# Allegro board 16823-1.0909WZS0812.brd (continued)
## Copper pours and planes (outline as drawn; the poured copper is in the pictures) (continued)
PWR_CHG_HIDRV on TOP: 163.25,162.79 163.11,162.93 163.11,165.06 163.23,165.18 163.91,165.18 164.09,165 164.09,162.84 164.04,162.79
PWR_CHG_LODRV on TOP: 170.09,158.63 170.01,158.7 170.01,160.5 170.03,160.53 171.3,160.53 171.41,160.43 171.41,158.75 171.28,158.63
PWR_CHG_PHASE on TOP: 167.32,161.01 167.14,161.19 167.14,162.69 167.01,162.82 164.32,162.82 164.29,162.84 164.29,164.67 164.37,164.75 166.53,164.75 166.68,164.9 166.68,169.88 166.96,170.16 171.43,170.16 171.66,169.93 171.66,161.57 171.1,161.01
PWR_CHG_PHASE on BOTTOM: 170.06,163.17 169.98,163.25 169.98,164.09 169.83,164.24 166.86,164.24 166.68,164.42 166.68,169.88 166.96,170.16 171.43,170.16 171.66,169.93 171.66,163.27 171.56,163.17
PWR_DCBATOUT_3D3V on TOP: 41.56,54.66 41.36,54.87 41.36,58.68 41.54,58.85 49.38,58.85 49.61,58.63 49.61,54.71 49.56,54.66 ; 2 cut-outs
PWR_DCBATOUT_5V on TOP: 41.43,38.58 41.36,38.66 41.36,42.39 41.43,42.47 49.49,42.47 49.61,42.34 49.61,38.76 49.44,38.58 ; 2 cut-outs
PWR_DCBATOUT_VCCGI on TOP: 111.95,125.73 111.64,126.04 111.64,134.95 111.72,135.03 115.4,135.03 115.53,134.9 115.53,131.29 115.3,131.07 115.3,125.76 115.27,125.73
PWR_DCBATOUT_VCCGI on BOTTOM: 114.43,125.73 114.41,125.76 114.41,127.13 114.23,127.31 111.87,127.31 111.64,127.54 111.64,135.74 111.72,135.82 115.37,135.82 115.53,135.66 115.53,131.29 115.3,131.07 115.3,125.76 115.27,125.73
PWR_DCBATOUT_VDDQ on TOP: 60,30.41 59.88,30.53 59.88,32.77 58.02,34.62 57.31,34.62 57.21,34.72 57.21,35.87 57.23,35.89 62.57,35.89 62.77,35.69 62.77,34.5 62.78,34.48 62.78,34.2 63.1,33.89 65.74,33.89 65.95,33.68 65.95,30.79 65.56,30.41
PWR_DCBATOUT_VNN on TOP: 107.12,127.84 106.97,127.99 106.97,133.68 107.09,133.81 111.28,133.81 111.44,133.66 111.44,128.2 111.08,127.84
PWR_VCCGI_PH on TOP: 114.08,121.85 113.8,122.13 113.8,125.33 113.98,125.5 115.53,125.5 115.68,125.66 115.68,130.94 115.81,131.07 118.6,131.07 118.68,130.99 118.68,126.14 119.01,125.81 119.44,125.81 119.51,125.73 119.51,125.3 119.82,125 120.15,125 120.33,124.82 120.33,121.92 120.25,121.85 ; 1 cut-out
PWR_VCCGI_PH on BOTTOM: 114.08,121.85 113.8,122.13 113.8,125.33 113.98,125.5 115.53,125.5 115.68,125.66 115.68,130.94 115.81,131.07 118.6,131.07 118.68,130.99 118.68,126.14 119.01,125.81 119.44,125.81 120.33,124.92 120.33,121.92 120.25,121.85
PWR_VCCRAM_PH on BOTTOM: 138.67,126.24 138.39,126.52 138.39,128.2 137.98,128.6 136.05,128.6 136,128.65 136,129.16 136.05,129.21 139.83,129.21 139.91,129.14 139.91,126.32 139.83,126.24
PWR_VDDQ on TOP: 73.41,40.85 73.24,41.02 73.24,43.97 73.25,43.98 73.25,46.46 74.33,47.54 74.33,52.58 77.86,56.11 82.74,56.11 83.04,55.81 83.04,54.15 83.34,53.85 90.76,53.85 90.96,53.65 90.96,43.74 90.36,43.13 83.5,43.13 81.21,40.85 ; 12 cut-outs
PWR_VDDQ on BOTTOM: 69.43,40.77 69.3,40.9 69.3,43.08 69.88,43.66 69.88,45.16 70.16,45.44 74.84,45.44 75.14,45.14 75.14,40.97 74.94,40.77 ; 5 cut-outs
PWR_VDDQ_PH on TOP: 66.4,30.33 66.33,30.41 66.33,32.06 66.4,32.13 67.55,32.13 67.8,32.39 67.8,33.94 67.42,34.32 64.62,34.32 64.55,34.39 64.55,37.77 64.6,37.82 73.03,37.82 73.29,37.57 73.29,30.96 72.65,30.33
PWR_VDDQ_PH on BOTTOM: 68.21,30.86 67.47,31.6 67.47,37.67 67.57,37.77 73.08,37.77 73.29,37.57 73.29,31.83 72.32,30.86
PWR_VNN_PH on TOP: 100.64,124.51 100.49,124.67 100.49,129.08 100.59,129.19 103.84,129.19 103.99,129.03 103.99,127.64 104.25,127.38 109.25,127.38 109.3,127.33 109.3,124.87 108.95,124.51 ; 2 cut-outs
PWR_VNN_PH on BOTTOM: 100.67,124.51 100.52,124.67 100.52,127.13 100.77,127.38 109.25,127.38 109.3,127.33 109.3,124.84 108.97,124.51
RING2 on TOP: 169.86,15.67 169.63,15.9 168.43,15.9 166.33,18.01 166.33,19.41 165.36,20.37 165.36,21.31 165.56,21.52 166.4,21.52 166.5,21.41 166.5,20.73 167.93,19.31 167.93,18.24 168.66,17.5 169.48,17.5 169.76,17.22 171.1,17.22 171.28,17.05 171.28,15.9 171.05,15.67 ; 1 cut-out
RING2_R on TOP: 171.56,16.08 171.41,16.23 171.41,17.07 171.51,17.17 173.9,17.17 173.97,17.1 173.97,16.13 173.92,16.08
RING2_R on BOTTOM: 171.25,15.9 171.13,16.03 171.13,16.99 171.33,17.2 173.49,17.2 173.64,17.05 173.64,16.08 173.46,15.9
RTC_AUX_S5 on BOTTOM: 102.67,97.13 102.39,97.16 101.89,97.79 101.89,97.92 101.99,98.1 103.13,99.01 103.46,98.96 103.82,98.96 104.33,99.27 104.45,99.27 104.73,98.94 104.73,98.81 104.66,98.68 102.9,97.16
SLEEVE on TOP: 169.78,17.5 169.58,17.71 169.58,18.85 167.9,20.53 167,20.53 166.75,20.78 166.75,21.66 166.94,21.85 168.33,21.85 170.21,19.97 171.28,19.97 171.43,19.81 171.43,17.68 171.25,17.5 ; 2 cut-outs
SLEEVE_R on TOP: 171.94,17.43 171.81,17.55 171.81,18.93 172.04,19.15 173.46,19.15 173.67,18.95 174.31,18.95 174.57,18.7 174.57,17.67 174.33,17.43 ; 1 cut-out
SLEEVE_R on BOTTOM: 171.28,17.38 171.13,17.53 171.13,18.54 171.29,18.71 173.78,18.71 173.86,18.63 173.86,17.53 173.84,17.53 173.69,17.38
TP_VDD on BOTTOM: 132.09,17.53 132.09,22.07 131.76,22.4 131.76,24.16 131.81,24.21 133.03,24.21 133.28,23.95 133.28,22.05 133.48,21.85 133.48,20.07 133.71,19.84 137.01,19.84 137.27,20.09 137.27,21.03 137.45,21.21 138.59,21.21 138.67,21.13 138.67,19.99 138.95,19.71 138.95,19.26 138.84,19.15 136.23,19.15 135.49,18.42 133.74,18.42 133.54,18.21 133.54,17.53 133.46,17.45 132.16,17.45 ; 4 cut-outs
TP_VDD on BOTTOM: 140.85,22.46 141.23,22.84 144.48,22.84 144.51,22.81 144.51,22.46 144.48,22.43 141.38,22.43 141.31,22.35 141.31,20.96 141.66,20.6 142.43,20.6 142.48,20.55 142.48,19.53 141.61,18.67 141.61,14.51 142.22,13.9 142.22,13.49 142.15,13.41 140.9,13.41 140.85,13.46
TPAN_VDD on TOP: 120.54,170.78 120.48,170.84 120.48,172.7 119.57,173.61 119.57,176.35 119.69,176.48 120.89,176.48 121.8,175.57 124.24,175.57 124.37,175.44 124.37,172.44 125.18,171.63 125.97,171.63 126.09,171.5 126.09,170.84 126.03,170.78 ; 1 cut-out
TPAN_VDD on BOTTOM: 119.64,173.38 119.19,173.47 118.45,173.99 117.96,175.21 117.66,176.05 117.66,176.1 117.91,176.2 117.96,176.18 118.02,176.05 118.27,175.36 118.4,175.24 118.75,175.19 120.05,175.19 120.18,175.11 120.69,173.89 120.66,173.76 120.25,173.54 120.22,173.52 120.06,173.43
TPAN_VDD_F on TOP: 120.86,165.81 120.53,166.14 120.53,170.13 120.68,170.28 126.12,170.28 126.19,170.21 126.19,166.04 125.97,165.81 ; 4 cut-outs
USB20_VCCA on TOP: 173.06,22.05 172.83,22.28 172.83,24.13 173.01,24.31 175.65,24.31 175.88,24.08 175.88,22.2 175.72,22.05 ; 2 cut-outs
USB20_VCCA on BOTTOM: 173.06,22.05 172.7,22.4 171.3,22.4 171.18,22.53 171.18,24.13 171.25,24.21 174.33,24.21 174.43,24.11 174.43,22.28 174.2,22.05
USB20_VCCA on BOTTOM: 167.22,9.15 166.9,9.46 165.63,9.46 164.98,10.11 163.2,10.11 163.15,10.16 163.15,11.13 163.23,11.2 165.06,11.2 165.39,10.87 167.67,10.87 167.8,10.75 167.8,9.27 167.67,9.15
USB20_VCCA on L4: 174.51,21.62 174.23,21.9 172.83,21.9 172.6,22.13 172.6,24.06 172.73,24.18 175.42,24.18 177.11,22.49 177.11,11.65 174.28,8.82 167.09,8.82 166.94,8.97 166.94,10.72 167.06,10.85 168.05,10.85 168.28,11.08 173.29,11.08 174.76,12.55 174.76,18.52 174.51,18.77

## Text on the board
Ref Des/Silkscreen Bottom: X1801:32.768KHZ | M2L3 | IOBD | X1901:19.2MHZ | HDD | ONLY | 15 | DCIN2 | SPK
Ref Des/Silkscreen Top: F5501:1.1A/24V | F5502:.5A/6V | F5503:1.1A/24V | 16823-1 | GFV07 | MADE IN TAIWAN | Turis_APL
User.30: ByImpedance:100.0@_REF_L1=("4.0/6.0(L1)" "3.5/5.0(L1)" "5.0/11.0(L1)")|_REF_L6=("4.0/6.0(L6)" "3.5/5.0(L6)" "5.0/11.0(L6)")|Type="DP"|_REF_L4=("4.0/9.0(L4)" "3.5/7.0(L4)")|_REF_L3=("4.0/9.0(L3)" "3.5/7.0(L3)")|imp="100.0" | ByImpedance:110.0@_REF_L1=("4.0/12.0(L1)")|_REF_L6=("4.0/12.0(L6)")|Type="DP"|_REF_L4=("3.5/13.0(L4)")|_REF_L3=("3.5/13.0(L3)")|imp="110.0" | ByImpedance:33.0@_REF_L1=("12.0(L1)")|_REF_L6=("12.0(L6)")|Type="SE"|_REF_L4=("12.5(L4)")|_REF_L3=("12.5(L3)")|imp="33.0" | ByImpedance:35.0@_REF_L1=("11.0(L1)")|_REF_L6=("11.0(L6)")|Type="SE"|_REF_L4=("10.5(L4)")|_REF_L3=("10.5(L3)")|imp="35.0" | ByImpedance:37.5@_REF_L1=("10.0(L1)")|_REF_L6=("10.0(L6)")|Type="SE"|_REF_L4=("9.5(L4)")|_REF_L3=("9.5(L3)")|imp="37.5" | ByImpedance:40.0@_REF_L1=("8.5(L1)")|_REF_L6=("8.5(L6)")|Type="SE"|_REF_L4=("8.0(L4)")|_REF_L3=("8.0(L3)")|imp="40.0" | ByImpedance:42.0@_REF_L1=("8.0(L1)")|_REF_L6=("8.0(L6)")|Type="SE"|_REF_L4=("7.5(L4)")|_REF_L3=("7.5(L3)")|imp="42.0" | ByImpedance:45.0@_REF_L1=("7.0(L1)")|_REF_L6=("7.0(L6)")|Type="SE"|_REF_L4=("6.5(L4)")|_REF_L3=("6.5(L3)")|imp="45.0" | ByImpedance:48.0@_REF_L1=("6.0(L1)")|_REF_L6=("6.0(L6)")|Type="SE"|_REF_L4=("5.5(L4)")|_REF_L3=("5.5(L3)")|imp="48.0" | ByImpedance:50.0@_REF_L1=("5.5(L1)" "5.5(L1)")|_REF_L6=("5.5(L6)" "5.5(L6)")|Type="SE"|_REF_L4=("5.0(L4)")|_REF_L3=("5.0(L3)")|imp="50.0" | ByImpedance:52.0@_REF_L1=("5.0(L1)")|_REF_L6=("5.0(L6)")|Type="SE"|_REF_L4=("4.5(L4)")|_REF_L3=("4.5(L3)")|imp="52.0" | ByImpedance:55.0@_REF_L1=("4.5(L1)")|_REF_L6=("4.5(L6)")|Type="SE"|_REF_L4=("4.0(L4)")|_REF_L3=("4.0(L3)")|imp="55.0" | ByImpedance:60.0@_REF_L1=("3.5(L1)")|_REF_L6=("3.5(L6)")|Type="SE"|imp="60.0" | ByImpedance:65.0@_REF_L1=("10.0/5.0(L1)")|_REF_L6=("10.0/5.0(L6)")|Type="DP"|_REF_L4=("9.0/5.0(L4)")|_REF_L3=("9.0/5.0(L3)")|imp="65.0" | ByImpedance:70.0@_REF_L1=("8.5/5.0(L1)")|_REF_L6=("8.5/5.0(L6)")|Type="DP"|_REF_L4=("8.0/5.0(L4)")|_REF_L3=("8.0/5.0(L3)")|imp="70.0" | ByImpedance:72.0@_REF_L1=("8.0/5.0(L1)")|_REF_L6=("8.0/5.0(L6)")|Type="DP"|_REF_L4=("7.0/5.0(L4)")|_REF_L3=("7.0/5.0(L3)")|imp="72.0" | ByImpedance:75.0@_REF_L1=("7.0/4.5(L1)")|_REF_L6=("7.0/4.5(L6)")|Type="DP"|_REF_L4=("7.0/6.0(L4)")|_REF_L3=("7.0/6.0(L3)")|imp="75.0" | ByImpedance:80.0@_REF_L1=("6.0/4.5(L1)")|_REF_L6=("6.0/4.5(L6)")|Type="DP"|_REF_L4=("5.5/5.0(L4)" "6.0/6.0(L4)" "5.0/4.0(L4)")|_REF_L3=("5.5/5.0(L3)" "6.0/6.0(L3)" "5.0/4.0(L3)")|imp="80.0" | ByImpedance:83.0@_REF_L1=("5.0/4.0(L1)")|_REF_L6=("5.0/4.0(L6)")|Type="DP"|_REF_L4=("4.5/4.0(L4)")|_REF_L3=("4.5/4.0(L3)")|imp="83.0" | ByImpedance:85.0@_REF_L1=("5.5/5.0(L1)" "5.0/4.5(L1)" "6.0/6.0(L1)")|_REF_L6=("5.5/5.0(L6)" "5.0/4.5(L6)" "6.0/6.0(L6)")|Type="DP"|_REF_L4=("5.5/7.0(L4)" "5.0/5.5(L4)" "4.5/4.5(L4)")|_REF_L3=("5.5/7.0(L3)" "5.0/5.5(L3)" "4.5/4.5(L3)")|imp="85.0" | ByImpedance:88.0@_REF_L1=("5.0/5.0(L1)" "4.5/4.0(L1)")|_REF_L6=("5.0/5.0(L6)" "4.5/4.0(L6)")|Type="DP"|_REF_L4=("4.0/4.5(L4)" "5.0/7.0(L4)")|_REF_L3=("4.0/4.5(L3)" "5.0/7.0(L3)")|imp="88.0" | ByImpedance:90.0@_REF_L1=("4.0/4.0(L1)" "5.0/6.0(L1)")|_REF_L6=("4.0/4.0(L6)" "5.0/6.0(L6)")|Type="DP"|_REF_L4=("5.0/8.0(L4)" "4.0/5.0(L4)" "4.5/6.0(L4)")|_REF_L3=("5.0/8.0(L3)" "4.0/5.0(L3)" "4.5/6.0(L3)")|imp="90.0" | ByImpedance:93.0@_REF_L1=("4.0/4.5(L1)" "5.0/6.5(L1)")|_REF_L6=("4.0/4.5(L6)" "5.0/6.5(L6)")|Type="DP"|_REF_L4=("4.0/6.0(L4)")|_REF_L3=("4.0/6.0(L3)")|imp="93.0" | ByImpedance:95.0@_REF_L1=("4.5/6.0(L1)")|_REF_L6=("4.5/6.0(L6)")|Type="DP"|_REF_L4=("4.0/6.5(L4)")|_REF_L3=("4.0/6.5(L3)")|imp="95.0" | LayerIndex:nil | Source:6-1.2-3l.xls | artWorks:("_REF_L3" "_REF_L4" "_REF_L6" "_REF_L1") | gtImpOutlineUsed:BOARD GEOMETRY/PANEL_OUTLINE
User.31: Board Accuracy Check,Aug 01 19:43:58 2016,Passed | Dummy-Static-No Shape On Layer Check,Aug 01 19:43:58 2016,Passed | Split Plane Check,Jun 06 17:11:58 2016,Passed
User.33: This gerber is just for your reference to find the DP impedance traces in layer L1. | DP IMPEDANCE TABLE: L1 | * - Denotes that this Impedance | is NOT used | IMP(Ohm) | *65.0 | *70.0 | *72.0 | *75.0 | *80.0 | *83.0 | *85.0 | 85.0 | *88.0 | *90.0 | *93.0 | *95.0 | *100.0 | *110.0 | WIDTH(mils) | 10.0/5.0 | 8.5/5.0 | 8.0/5.0 | 7.0/4.5 | 6.0/4.5 | 5.0/4.0 | 5.5/5.0 | 5.0/4.5 | 6.0/6.0 | 5.0/5.0 | 4.5/4.0 | 4.0/4.0 | 5.0/6.0 | 4.0/4.5 | 5.0/6.5 | 4.5/6.0 | 4.0/6.0 | 3.5/5.0 | 5.0/11.0 | 4.0/12.0 | TYPE | DP
User.35: This gerber is just for your reference to find the SE impedance traces in layer L1. | SE IMPEDANCE TABLE: L1 | * - Denotes that this Impedance | is NOT used | IMP(Ohm) | *33.0 | *35.0 | *37.5 | *40.0 | 42.0 | *45.0 | *48.0 | 50.0 | *52.0 | *55.0 | *60.0 | WIDTH(mils) | 12.0 | 11.0 | 10.0 | 8.5 | 8.0 | 7.0 | 6.0 | 5.5 | 5.0 | 4.5 | 3.5 | TYPE | SE
User.37: This gerber is just for your reference to find the DP impedance traces in layer L3. | DP IMPEDANCE TABLE: L3 | * - Denotes that this Impedance | is NOT used | IMP(Ohm) | *65.0 | *70.0 | *72.0 | *75.0 | *80.0 | *83.0 | *85.0 | 85.0 | *88.0 | *90.0 | *93.0 | *95.0 | *100.0 | *110.0 | WIDTH(mils) | 9.0/5.0 | 8.0/5.0 | 7.0/5.0 | 7.0/6.0 | 5.5/5.0 | 6.0/6.0 | 5.0/4.0 | 4.5/4.0 | 5.5/7.0 | 5.0/5.5 | 4.5/4.5 | 4.0/4.5 | 5.0/7.0 | 5.0/8.0 | 4.0/5.0 | 4.5/6.0 | 4.0/6.0 | 4.0/6.5 | 4.0/9.0 | 3.5/7.0 | 3.5/13.0 | TYPE | DP
User.39: This gerber is just for your reference to find the SE impedance traces in layer L3. | SE IMPEDANCE TABLE: L3 | * - Denotes that this Impedance | is NOT used | IMP(Ohm) | *33.0 | *35.0 | *37.5 | *40.0 | 42.0 | *45.0 | *48.0 | 50.0 | *52.0 | *55.0 | WIDTH(mils) | 12.5 | 10.5 | 9.5 | 8.0 | 7.5 | 6.5 | 5.5 | 5.0 | 4.5 | 4.0 | TYPE | SE
User.41: This gerber is just for your reference to find the DP impedance traces in layer L4. | DP IMPEDANCE TABLE: L4 | * - Denotes that this Impedance | is NOT used | IMP(Ohm) | *65.0 | *70.0 | *72.0 | *75.0 | *80.0 | *83.0 | *85.0 | 85.0 | *88.0 | *90.0 | *93.0 | *95.0 | *100.0 | *110.0 | WIDTH(mils) | 9.0/5.0 | 8.0/5.0 | 7.0/5.0 | 7.0/6.0 | 5.5/5.0 | 6.0/6.0 | 5.0/4.0 | 4.5/4.0 | 5.5/7.0 | 5.0/5.5 | 4.5/4.5 | 4.0/4.5 | 5.0/7.0 | 5.0/8.0 | 4.0/5.0 | 4.5/6.0 | 4.0/6.0 | 4.0/6.5 | 4.0/9.0 | 3.5/7.0 | 3.5/13.0 | TYPE | DP
User.43: This gerber is just for your reference to find the SE impedance traces in layer L4. | SE IMPEDANCE TABLE: L4 | * - Denotes that this Impedance | is NOT used | IMP(Ohm) | *33.0 | *35.0 | *37.5 | *40.0 | 42.0 | *45.0 | *48.0 | 50.0 | *52.0 | *55.0 | WIDTH(mils) | 12.5 | 10.5 | 9.5 | 8.0 | 7.5 | 6.5 | 5.5 | 5.0 | 4.5 | 4.0 | TYPE | SE
User.45: Note:Refer to DRILL layer for ELLIPSE drill direction | FIGURE | SIZE | 10.0 | 12.0 | 16.0 | 21.0 | 28.0 | 35.0 | 40.0 | 91.0 | 115.0 | 128.0 | 178.0 | 36.0 | 44.0 | 46.0 | 50.0 | 63.0 | 65.0 | 86.0 | 103.0 | 71.0x36.0 | 83.0x28.0 | 98.0x28.0 | 106.0x28.0 | 158.0x119.0 | DRILL CHART: TOP to BOTTOM | ALL UNITS ARE IN MILS | PLATED | NON-PLATED | QTY | 2399 | 2 | 440 | 19 | 18 | 8 | 1 | 5 | 4 | This gerber is just for your reference to find the DP impedance traces in layer L6. | This gerber is just for your reference to find the SE impedance traces in layer L6. | DP IMPEDANCE TABLE: L6 | SE IMPEDANCE TABLE: L6 | * - Denotes that this Impedance | is NOT used | Model | Turis14APL | PCB_NO | 16823 | VER. | SC | Layer | DRILL | L1 | L2VCC | L3 | TMASK | TPLACE | TSILK | TSMD | Designer | CICI CHEN | IMP(Ohm) | *33.0 | *65.0 | *35.0 | *70.0 | *37.5 | *72.0 | *40.0 | *75.0 | *80.0 | 42.0 | *45.0 | *83.0 | *48.0 | *85.0 | 85.0 | *52.0 | *88.0 | *55.0 | *60.0 | *90.0 | *93.0 | *95.0 | *100.0 | *110.0 | Date | 08/01/2016 | WIDTH(mils) | 11.0 | 8.5 | 8.0 | 7.0 | 6.0 | 5.5 | 5.0 | 4.5 | 3.5 | 10.0/5.0 | 8.5/5.0 | 8.0/5.0 | 7.0/4.5 | 6.0/4.5 | 5.0/4.0 | 5.5/5.0 | 5.0/4.5 | 6.0/6.0 | 5.0/5.0 | 4.5/4.0 | 4.0/4.0 | 5.0/6.0 | 4.0/4.5 | 5.0/6.5 | 4.5/6.0 | 4.0/6.0 | 3.5/5.0 | 5.0/11.0 | 4.0/12.0 | TYPE | SE | DP | BMASK | BPLACE | BSILK | BSMD | L4 | L5GND | L6
